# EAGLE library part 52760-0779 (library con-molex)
MOLEX Connector SD-52760-**79 Source: 52760-1079_sd molex.pdf
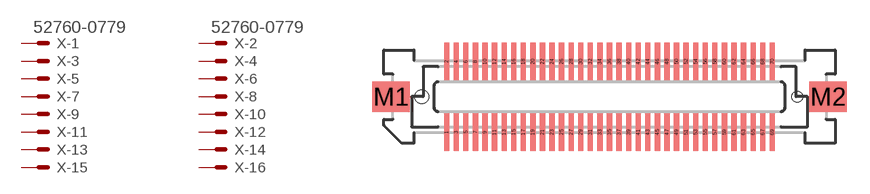
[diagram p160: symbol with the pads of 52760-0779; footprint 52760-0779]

Designator prefix X; gates -1=MV -2=MV -3=M -4=M -5=M -6=M -7=M -8=M -9=M -10=M -11=M -12=M -13=M -14=M -15=M -16=M -17=M -18=M -19=M -20=M -21=M -22=M -23=M -24=M -25=M -26=M -27=M -28=M -29=M -30=M -31=M -32=M -33=M -34=M -35=M -36=M -37=M -38=M -39=M -40=M -41=M -42=M -43=M -44=M -45=M -46=M -47=M -48=M -49=M -50=M -51=M -52=M -53=M -54=M -55=M -56=M -57=M -58=M -59=M -60=M -61=M -62=M -63=M -64=M -65=M -66=M -67=M -68=M -69=M -70=M

## 52760-0779 (OC_FARNELL: unknown; OC_NEWARK: unknown)  [52760-0779]
1  -1:S  pas
2  -2:S  pas
3  -3:S  pas
4  -4:S  pas
5  -5:S  pas
6  -6:S  pas
7  -7:S  pas
8  -8:S  pas
9  -9:S  pas
10  -10:S  pas
11  -11:S  pas
12  -12:S  pas
13  -13:S  pas
14  -14:S  pas
15  -15:S  pas
16  -16:S  pas
17  -17:S  pas
18  -18:S  pas
19  -19:S  pas
20  -20:S  pas
21  -21:S  pas
22  -22:S  pas
23  -23:S  pas
24  -24:S  pas
25  -25:S  pas
26  -26:S  pas
27  -27:S  pas
28  -28:S  pas
29  -29:S  pas
30  -30:S  pas
31  -31:S  pas
32  -32:S  pas
33  -33:S  pas
34  -34:S  pas
35  -35:S  pas
36  -36:S  pas
37  -37:S  pas
38  -38:S  pas
39  -39:S  pas
40  -40:S  pas
41  -41:S  pas
42  -42:S  pas
43  -43:S  pas
44  -44:S  pas
45  -45:S  pas
46  -46:S  pas
47  -47:S  pas
48  -48:S  pas
49  -49:S  pas
50  -50:S  pas
51  -51:S  pas
52  -52:S  pas
53  -53:S  pas
54  -54:S  pas
55  -55:S  pas
56  -56:S  pas
57  -57:S  pas
58  -58:S  pas
59  -59:S  pas
60  -60:S  pas
61  -61:S  pas
62  -62:S  pas
63  -63:S  pas
64  -64:S  pas
65  -65:S  pas
66  -66:S  pas
67  -67:S  pas
68  -68:S  pas
69  -69:S  pas
70  -70:S  pas

## Footprint 52760-0779 (pad centres in mm)
MOLEX Connector SD-52760-**79 Source: 52760-1079_sd molex.pdf
smd 0.35 x 2.5: 1 -10.795,-2.35; 2 -10.795,2.35; 3 -10.16,-2.35; 4 -10.16,2.35; 5 -9.525,-2.35; 6 -9.525,2.35; 7 -8.89,-2.35; 8 -8.89,2.35; 9 -8.255,-2.35; 10 -8.255,2.35; 11 -7.62,-2.35; 12 -7.62,2.35; 13 -6.985,-2.35; 14 -6.985,2.35; 15 -6.35,-2.35; 16 -6.35,2.35; 17 -5.715,-2.35; 18 -5.715,2.35; 19 -5.08,-2.35; 20 -5.08,2.35; 21 -4.445,-2.35; 22 -4.445,2.35; 23 -3.81,-2.35; 24 -3.81,2.35; 25 -3.175,-2.35; 26 -3.175,2.35; 27 -2.54,-2.35; 28 -2.54,2.35; 29 -1.905,-2.35; 30 -1.905,2.35; 31 -1.27,-2.35; 32 -1.27,2.35; 33 -0.635,-2.35; 34 -0.635,2.35; 35 0,-2.35; 36 0,2.35; 37 0.635,-2.35; 38 0.635,2.35; 39 1.27,-2.35; 40 1.27,2.35; 41 1.905,-2.35; 42 1.905,2.35; 43 2.54,-2.35; 44 2.54,2.35; 45 3.175,-2.35; 46 3.175,2.35; 47 3.81,-2.35; 48 3.81,2.35; 49 4.445,-2.35; 50 4.445,2.35; 51 5.08,-2.35; 52 5.08,2.35; 53 5.715,-2.35; 54 5.715,2.35; 55 6.35,-2.35; 56 6.35,2.35; 57 6.985,-2.35; 58 6.985,2.35; 59 7.62,-2.35; 60 7.62,2.35; 61 8.255,-2.35; 62 8.255,2.35; 63 8.89,-2.35; 64 8.89,2.35; 65 9.525,-2.35; 66 9.525,2.35; 67 10.16,-2.35; 68 10.16,2.35; 69 10.795,-2.35; 70 10.795,2.35
smd 2.5 x 2: M1 -14.488,0; M2 14.488,0
hole 0.9 at -12.447,0
hole 0.7 at 12.447,0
